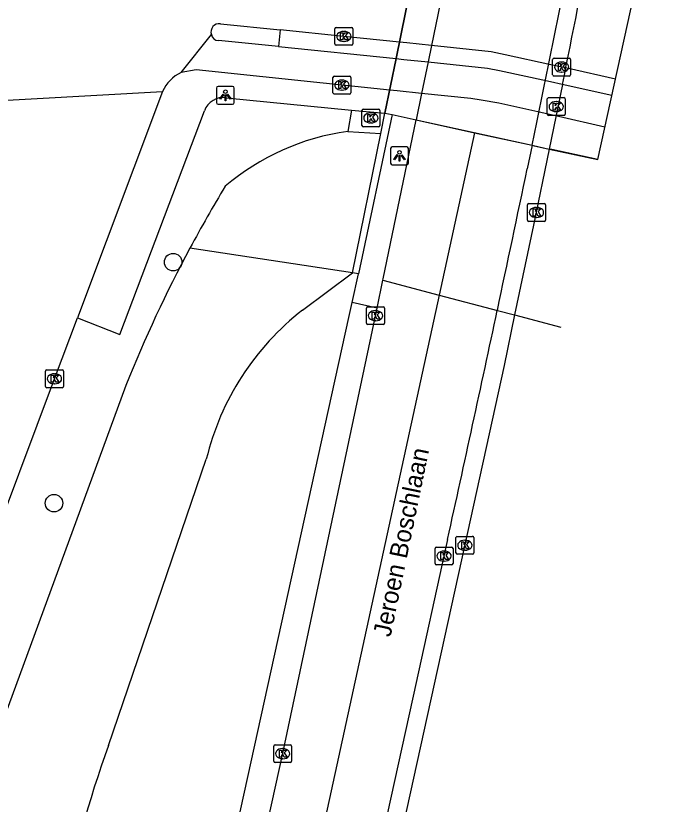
# Model space of a CAD drawing. Extents: x 162172 to 163187, y 382874 to 383684.
# Drawn here: x 163131.97 to 163168.94, y 383006.21 to 383050.22 of the extents above; entities that cross this region are included whole.
import ezdxf

# ---------------------------------------------------------------- set-up
doc = ezdxf.new("R2010")
doc.units = 0
for name, color, linetype in [('IMGEO_Berm_gesloten', 7, 'Continuous'), ('IMGEO_Berm_groen', 7, 'Continuous'), ('IMGEO_Berm_open', 7, 'Continuous'), ('IMGEO_Boom', 7, 'Continuous'), ('IMGEO_Dek', 7, 'Continuous'), ('IMGEO_Fietspad_open', 7, 'Continuous'), ('IMGEO_Hek', 7, 'Continuous'), ('IMGEO_Kolk', 7, 'Continuous'), ('IMGEO_Lichtpunt', 7, 'Continuous'), ('IMGEO_Muur', 7, 'Continuous'), ('IMGEO_Openbare_ruimte_label', 7, 'Continuous'), ('IMGEO_Rijbaan_lokaal_gesloten', 7, 'Continuous'), ('IMGEO_Rijbaan_lokaal_open', 7, 'Continuous'), ('IMGEO_Rijbaan_regionaal_gesloten', 7, 'Continuous'), ('IMGEO_Verkeerseiland_open', 7, 'Continuous'), ('IMGEO_Voetpad_open', 7, 'Continuous')]:
    doc.layers.add(name, color=color, linetype=linetype)

msp = doc.modelspace()

# ---------------------------------------------------------------- linework, layer by layer
at = {"layer": 'IMGEO_Berm_gesloten'}
msp.add_lwpolyline([(163158.847, 383033.776), (163159.814, 383033.521)], dxfattribs=at)
at = {"layer": 'IMGEO_Berm_groen'}
for points in [[(163150.71, 383044.959), (163150.497, 383043.765)], [(163147.971, 383033.794), (163150.756, 383035.866)], [(163132.311, 382950.327), (163150.561, 383033.379), (163150.743, 383034.209)], [(163138.112, 383029.587), (163130.709, 383009.426)], [(163137.146, 383009.486), (163142.599, 383025.464)]]:
    msp.add_lwpolyline(points, dxfattribs=at)
for centre, radius, start, end in [((163208.22, 383001.542), 75.51, 151.77482, 158.19712), ((163157.287, 383021.889), 15.117, 128.0444, 166.3198), ((163191.568, 382989.56), 57.955, 159.89074, 169.62253)]:
    msp.add_arc(centre, radius, start, end, dxfattribs=at)
at = {"layer": 'IMGEO_Berm_open'}
for points in [[(163158.23, 383064.942), (163156.885, 383065.236), (163156.496, 383065.321), (163156.083, 383063.015), (163155.711, 383060.937), (163155.55, 383060.039), (163154.667, 383055.107), (163154.492, 383054.187), (163153.196, 383047.828), (163152.574, 383044.776), (163152.973, 383044.701), (163154.313, 383044.408)], [(163150.497, 383043.765), (163152.344, 383043.65)], [(163160.79, 383042.99), (163161.74, 383042.782)], [(163150.756, 383035.866), (163141.689, 383037.253)], [(163150.743, 383034.209), (163151.096, 383035.814)], [(163152.139, 383033.902), (163150.743, 383034.209)]]:
    msp.add_lwpolyline(points, dxfattribs=at)
for centre, radius, start, end in [((163152.32, 383030.535), 13.355, 97.8457, 130.4348), ((163209.121, 383001.02), 76.55, 148.77827, 151.74987)]:
    msp.add_arc(centre, radius, start, end, dxfattribs=at)
at = {"layer": 'IMGEO_Boom'}
for centre in [(163140.748, 383036.468), (163134.101, 383023.01)]:
    msp.add_circle(centre, 0.489, dxfattribs=at)
at = {"layer": 'IMGEO_Dek'}
msp.add_lwpolyline([(163164.453, 383042.189), (163166.656, 383052.2), (163168.944, 383062.596), (163168.818, 383062.624), (163165.733, 383063.299), (163164.764, 383063.511), (163158.23, 383064.942), (163156.885, 383065.236), (163156.496, 383065.321), (163156.083, 383063.015), (163155.711, 383060.937), (163155.55, 383060.039), (163154.667, 383055.107), (163154.492, 383054.187), (163153.196, 383047.828), (163152.574, 383044.776), (163152.973, 383044.701), (163154.313, 383044.408), (163160.79, 383042.99), (163161.74, 383042.782), (163164.453, 383042.189)], dxfattribs=at)
at = {"layer": 'IMGEO_Fietspad_open'}
for points in [[(163146.629, 383048.51), (163143.275, 383048.842)], [(163146.629, 383048.51), (163153.196, 383047.828), (163153.618, 383047.784), (163154.983, 383047.642), (163158.292, 383047.294), (163158.975, 383047.168), (163161.644, 383046.581), (163162.627, 383046.365), (163165.245, 383045.789)], [(163164.853, 383044.008), (163162.269, 383044.59), (163161.283, 383044.812), (163158.936, 383045.34), (163157.941, 383045.503), (163157.376, 383045.596), (163154.619, 383045.886), (163153.251, 383046.029), (163152.839, 383046.073), (163142.029, 383047.204), (163141.189, 383047.059)]]:
    msp.add_lwpolyline(points, dxfattribs=at)
msp.add_arc((163143.275, 383049.234), 0.392, 189.5261, 269.9347, dxfattribs=at)
at = {"layer": 'IMGEO_Hek'}
for points in [[(163153.196, 383047.828), (163154.492, 383054.187)], [(163152.574, 383044.776), (163153.196, 383047.828)]]:
    msp.add_lwpolyline(points, dxfattribs=at)
at = {"layer": 'IMGEO_Kolk'}
for p, q in [((163149.779, 383048.645), (163149.779, 383049.497)), ((163149.854, 383049.571), (163150.706, 383049.571)), ((163150.267, 383049.351), (163150.292, 383049.351)), ((163150.78, 383049.497), (163150.78, 383048.645)), ((163150.706, 383048.571), (163149.854, 383048.571)), ((163150.29, 383048.791), (163150.265, 383048.791)), ((163161.935, 383046.932), (163161.935, 383047.784)), ((163162.01, 383047.858), (163162.862, 383047.858)), ((163162.423, 383047.638), (163162.448, 383047.638)), ((163162.936, 383047.784), (163162.936, 383046.932)), ((163162.446, 383047.078), (163162.421, 383047.078)), ((163149.671, 383045.926), (163149.671, 383046.778)), ((163149.746, 383046.852), (163150.598, 383046.852)), ((163150.159, 383046.632), (163150.184, 383046.632)), ((163150.672, 383046.778), (163150.672, 383045.926)), ((163162.862, 383046.858), (163162.01, 383046.858)), ((163150.598, 383045.852), (163149.746, 383045.852)), ((163150.182, 383046.072), (163150.157, 383046.072)), ((163161.635, 383044.724), (163161.635, 383045.576)), ((163161.71, 383045.65), (163162.562, 383045.65)), ((163162.123, 383045.43), (163162.148, 383045.43)), ((163162.636, 383045.576), (163162.636, 383044.724)), ((163151.288, 383044.089), (163151.288, 383044.941)), ((163151.363, 383045.015), (163152.215, 383045.015)), ((163152.289, 383044.941), (163152.289, 383044.089)), ((163162.146, 383044.87), (163162.121, 383044.87)), ((163151.776, 383044.795), (163151.801, 383044.795)), ((163162.562, 383044.65), (163161.71, 383044.65)), ((163152.215, 383044.015), (163151.363, 383044.015)), ((163151.799, 383044.235), (163151.774, 383044.235)), ((163160.53, 383038.814), (163160.53, 383039.666)), ((163160.605, 383039.74), (163161.457, 383039.74)), ((163161.531, 383039.666), (163161.531, 383038.814)), ((163161.018, 383039.52), (163161.043, 383039.52)), ((163161.457, 383038.74), (163160.605, 383038.74)), ((163161.041, 383038.96), (163161.016, 383038.96)), ((163151.545, 383033.053), (163151.545, 383033.905)), ((163151.62, 383033.979), (163152.472, 383033.979)), ((163152.546, 383033.905), (163152.546, 383033.053)), ((163152.033, 383033.759), (163152.058, 383033.759)), ((163152.472, 383032.979), (163151.62, 383032.979)), ((163152.056, 383033.199), (163152.031, 383033.199)), ((163133.625, 383029.533), (163133.625, 383030.385)), ((163133.7, 383030.459), (163134.552, 383030.459)), ((163134.626, 383030.385), (163134.626, 383029.533)), ((163134.113, 383030.239), (163134.138, 383030.239)), ((163134.552, 383029.459), (163133.7, 383029.459)), ((163134.136, 383029.679), (163134.111, 383029.679)), ((163156.536, 383020.235), (163156.536, 383021.087)), ((163156.611, 383021.161), (163157.463, 383021.161)), ((163157.537, 383021.087), (163157.537, 383020.235)), ((163157.024, 383020.941), (163157.049, 383020.941)), ((163155.371, 383019.636), (163155.371, 383020.488)), ((163155.446, 383020.562), (163156.298, 383020.562)), ((163155.859, 383020.342), (163155.884, 383020.342)), ((163156.372, 383020.488), (163156.372, 383019.636)), ((163157.047, 383020.381), (163157.022, 383020.381)), ((163155.882, 383019.782), (163155.857, 383019.782)), ((163157.463, 383020.161), (163156.611, 383020.161)), ((163156.298, 383019.562), (163155.446, 383019.562)), ((163146.363, 383008.603), (163146.363, 383009.455)), ((163146.438, 383009.529), (163147.29, 383009.529)), ((163146.851, 383009.309), (163146.876, 383009.309)), ((163147.364, 383009.455), (163147.364, 383008.603)), ((163146.874, 383008.749), (163146.849, 383008.749)), ((163147.29, 383008.529), (163146.438, 383008.529))]:
    msp.add_line(p, q, dxfattribs=at)
for points in [[(163149.779, 383048.645), (163149.779, 383049.497)], [(163149.854, 383049.571), (163150.706, 383049.571)], [(163150.1, 383049.271), (163150.223, 383049.271), (163150.223, 383049.12), (163150.353, 383049.271), (163150.517, 383049.271), (163150.371, 383049.12), (163150.524, 383048.871), (163150.372, 383048.871), (163150.287, 383049.035), (163150.223, 383048.968), (163150.223, 383048.871), (163150.1, 383048.871), (163150.1, 383049.271)], [(163150.78, 383049.497), (163150.78, 383048.645)], [(163150.706, 383048.571), (163149.854, 383048.571)], [(163161.935, 383046.932), (163161.935, 383047.784)], [(163162.01, 383047.858), (163162.862, 383047.858)], [(163162.256, 383047.558), (163162.379, 383047.558), (163162.379, 383047.407), (163162.509, 383047.558), (163162.673, 383047.558), (163162.527, 383047.407), (163162.68, 383047.158), (163162.528, 383047.158), (163162.443, 383047.322), (163162.379, 383047.255), (163162.379, 383047.158), (163162.256, 383047.158), (163162.256, 383047.558)], [(163162.936, 383047.784), (163162.936, 383046.932)], [(163149.671, 383045.926), (163149.671, 383046.778)], [(163149.746, 383046.852), (163150.598, 383046.852)], [(163150.672, 383046.778), (163150.672, 383045.926)], [(163162.862, 383046.858), (163162.01, 383046.858)], [(163149.992, 383046.552), (163150.115, 383046.552), (163150.115, 383046.401), (163150.245, 383046.552), (163150.409, 383046.552), (163150.263, 383046.401), (163150.416, 383046.152), (163150.264, 383046.152), (163150.179, 383046.316), (163150.115, 383046.249), (163150.115, 383046.152), (163149.992, 383046.152), (163149.992, 383046.552)], [(163150.598, 383045.852), (163149.746, 383045.852)], [(163161.635, 383044.724), (163161.635, 383045.576)], [(163161.71, 383045.65), (163162.562, 383045.65)], [(163161.956, 383045.35), (163162.079, 383045.35), (163162.079, 383045.199), (163162.209, 383045.35), (163162.373, 383045.35), (163162.227, 383045.199), (163162.38, 383044.95), (163162.228, 383044.95), (163162.143, 383045.114), (163162.079, 383045.047), (163162.079, 383044.95), (163161.956, 383044.95), (163161.956, 383045.35)], [(163162.636, 383045.576), (163162.636, 383044.724)], [(163151.288, 383044.089), (163151.288, 383044.941)], [(163151.363, 383045.015), (163152.215, 383045.015)], [(163152.289, 383044.941), (163152.289, 383044.089)], [(163151.609, 383044.715), (163151.732, 383044.715), (163151.732, 383044.564), (163151.862, 383044.715), (163152.026, 383044.715), (163151.88, 383044.564), (163152.033, 383044.315), (163151.881, 383044.315), (163151.796, 383044.479), (163151.732, 383044.412), (163151.732, 383044.315), (163151.609, 383044.315), (163151.609, 383044.715)], [(163162.562, 383044.65), (163161.71, 383044.65)], [(163152.215, 383044.015), (163151.363, 383044.015)], [(163160.53, 383038.814), (163160.53, 383039.666)], [(163160.605, 383039.74), (163161.457, 383039.74)], [(163161.531, 383039.666), (163161.531, 383038.814)], [(163160.851, 383039.44), (163160.974, 383039.44), (163160.974, 383039.289), (163161.104, 383039.44), (163161.268, 383039.44), (163161.122, 383039.289), (163161.275, 383039.04), (163161.123, 383039.04), (163161.038, 383039.204), (163160.974, 383039.137), (163160.974, 383039.04), (163160.851, 383039.04), (163160.851, 383039.44)], [(163161.457, 383038.74), (163160.605, 383038.74)], [(163151.545, 383033.053), (163151.545, 383033.905)], [(163151.62, 383033.979), (163152.472, 383033.979)], [(163152.546, 383033.905), (163152.546, 383033.053)], [(163151.866, 383033.679), (163151.989, 383033.679), (163151.989, 383033.528), (163152.119, 383033.679), (163152.283, 383033.679), (163152.137, 383033.528), (163152.29, 383033.279), (163152.138, 383033.279), (163152.053, 383033.443), (163151.989, 383033.376), (163151.989, 383033.279), (163151.866, 383033.279), (163151.866, 383033.679)], [(163152.472, 383032.979), (163151.62, 383032.979)], [(163133.625, 383029.533), (163133.625, 383030.385)], [(163133.7, 383030.459), (163134.552, 383030.459)], [(163134.626, 383030.385), (163134.626, 383029.533)], [(163133.946, 383030.159), (163134.069, 383030.159), (163134.069, 383030.008), (163134.199, 383030.159), (163134.363, 383030.159), (163134.217, 383030.008), (163134.37, 383029.759), (163134.218, 383029.759), (163134.133, 383029.923), (163134.069, 383029.856), (163134.069, 383029.759), (163133.946, 383029.759), (163133.946, 383030.159)], [(163134.552, 383029.459), (163133.7, 383029.459)], [(163156.536, 383020.235), (163156.536, 383021.087)], [(163156.611, 383021.161), (163157.463, 383021.161)], [(163157.537, 383021.087), (163157.537, 383020.235)], [(163156.857, 383020.861), (163156.98, 383020.861), (163156.98, 383020.71), (163157.11, 383020.861), (163157.274, 383020.861), (163157.128, 383020.71), (163157.281, 383020.461), (163157.129, 383020.461), (163157.044, 383020.625), (163156.98, 383020.558), (163156.98, 383020.461), (163156.857, 383020.461), (163156.857, 383020.861)], [(163155.371, 383019.636), (163155.371, 383020.488)], [(163155.446, 383020.562), (163156.298, 383020.562)], [(163155.692, 383020.262), (163155.815, 383020.262), (163155.815, 383020.111), (163155.945, 383020.262), (163156.109, 383020.262), (163155.963, 383020.111), (163156.116, 383019.862), (163155.964, 383019.862), (163155.879, 383020.026), (163155.815, 383019.959), (163155.815, 383019.862), (163155.692, 383019.862), (163155.692, 383020.262)], [(163156.372, 383020.488), (163156.372, 383019.636)], [(163157.463, 383020.161), (163156.611, 383020.161)], [(163156.298, 383019.562), (163155.446, 383019.562)], [(163146.363, 383008.603), (163146.363, 383009.455)], [(163146.438, 383009.529), (163147.29, 383009.529)], [(163146.684, 383009.229), (163146.807, 383009.229), (163146.807, 383009.078), (163146.937, 383009.229), (163147.101, 383009.229), (163146.955, 383009.078), (163147.108, 383008.829), (163146.956, 383008.829), (163146.871, 383008.993), (163146.807, 383008.926), (163146.807, 383008.829), (163146.684, 383008.829), (163146.684, 383009.229)], [(163147.364, 383009.455), (163147.364, 383008.603)], [(163147.29, 383008.529), (163146.438, 383008.529)]]:
    msp.add_lwpolyline(points, dxfattribs=at)
for centre, start, end in [((163149.856, 383049.495), 91.552, 178.448), ((163149.856, 383049.495), 91.552, 178.448), ((163150.704, 383049.495), 1.552, 88.448), ((163150.704, 383049.495), 1.552, 88.448), ((163149.856, 383048.647), 181.552, 268.448), ((163149.856, 383048.647), 181.552, 268.448), ((163150.704, 383048.647), 271.552, 358.448), ((163150.704, 383048.647), 271.552, 358.448), ((163162.012, 383047.782), 91.552, 178.448), ((163162.012, 383047.782), 91.552, 178.448), ((163162.86, 383047.782), 1.552, 88.448), ((163162.86, 383047.782), 1.552, 88.448), ((163149.748, 383046.776), 91.552, 178.448), ((163149.748, 383046.776), 91.552, 178.448), ((163150.596, 383046.776), 1.552, 88.448), ((163150.596, 383046.776), 1.552, 88.448), ((163162.012, 383046.934), 181.552, 268.448), ((163162.012, 383046.934), 181.552, 268.448), ((163162.86, 383046.934), 271.552, 358.448), ((163162.86, 383046.934), 271.552, 358.448), ((163149.748, 383045.928), 181.552, 268.448), ((163149.748, 383045.928), 181.552, 268.448), ((163150.596, 383045.928), 271.552, 358.448), ((163150.596, 383045.928), 271.552, 358.448), ((163161.712, 383045.574), 91.552, 178.448), ((163161.712, 383045.574), 91.552, 178.448), ((163162.56, 383045.574), 1.552, 88.448), ((163162.56, 383045.574), 1.552, 88.448), ((163151.365, 383044.939), 91.552, 178.448), ((163151.365, 383044.939), 91.552, 178.448), ((163152.213, 383044.939), 1.552, 88.448), ((163152.213, 383044.939), 1.552, 88.448), ((163161.712, 383044.726), 181.552, 268.448), ((163161.712, 383044.726), 181.552, 268.448), ((163162.56, 383044.726), 271.552, 358.448), ((163162.56, 383044.726), 271.552, 358.448), ((163151.365, 383044.091), 181.552, 268.448), ((163151.365, 383044.091), 181.552, 268.448), ((163152.213, 383044.091), 271.552, 358.448), ((163152.213, 383044.091), 271.552, 358.448), ((163160.607, 383039.664), 91.552, 178.448), ((163160.607, 383039.664), 91.552, 178.448), ((163161.455, 383039.664), 1.552, 88.448), ((163161.455, 383039.664), 1.552, 88.448), ((163160.607, 383038.816), 181.552, 268.448), ((163160.607, 383038.816), 181.552, 268.448), ((163161.455, 383038.816), 271.552, 358.448), ((163161.455, 383038.816), 271.552, 358.448), ((163151.622, 383033.903), 91.552, 178.448), ((163151.622, 383033.903), 91.552, 178.448), ((163152.47, 383033.903), 1.552, 88.448), ((163152.47, 383033.903), 1.552, 88.448), ((163151.622, 383033.055), 181.552, 268.448), ((163151.622, 383033.055), 181.552, 268.448), ((163152.47, 383033.055), 271.552, 358.448), ((163152.47, 383033.055), 271.552, 358.448), ((163133.702, 383030.383), 91.552, 178.448), ((163133.702, 383030.383), 91.552, 178.448), ((163134.55, 383030.383), 1.552, 88.448), ((163134.55, 383030.383), 1.552, 88.448), ((163133.702, 383029.535), 181.552, 268.448), ((163133.702, 383029.535), 181.552, 268.448), ((163134.55, 383029.535), 271.552, 358.448), ((163134.55, 383029.535), 271.552, 358.448), ((163156.613, 383021.085), 91.552, 178.448), ((163156.613, 383021.085), 91.552, 178.448), ((163157.461, 383021.085), 1.552, 88.448), ((163157.461, 383021.085), 1.552, 88.448), ((163155.448, 383020.486), 91.552, 178.448), ((163155.448, 383020.486), 91.552, 178.448), ((163156.296, 383020.486), 1.552, 88.448), ((163156.296, 383020.486), 1.552, 88.448), ((163156.613, 383020.237), 181.552, 268.448), ((163156.613, 383020.237), 181.552, 268.448), ((163157.461, 383020.237), 271.552, 358.448), ((163157.461, 383020.237), 271.552, 358.448), ((163155.448, 383019.638), 181.552, 268.448), ((163155.448, 383019.638), 181.552, 268.448), ((163156.296, 383019.638), 271.552, 358.448), ((163156.296, 383019.638), 271.552, 358.448), ((163146.44, 383009.453), 91.552, 178.448), ((163146.44, 383009.453), 91.552, 178.448), ((163147.288, 383009.453), 1.552, 88.448), ((163147.288, 383009.453), 1.552, 88.448), ((163146.44, 383008.605), 181.552, 268.448), ((163146.44, 383008.605), 181.552, 268.448), ((163147.288, 383008.605), 271.552, 358.448), ((163147.288, 383008.605), 271.552, 358.448)]:
    msp.add_arc(centre, 0.0765, start, end, dxfattribs=at)
for centre, major_axis, ratio, start_param, end_param in [((163150.266, 383049.071), (-0.387, 0.002), 0.722429, 4.712389, 7.853982), ((163150.291, 383049.071), (-0.39, 0.002), 0.717154, 1.570796, 4.712389), ((163162.422, 383047.358), (-0.387, 0.002), 0.722429, 4.712389, 7.853982), ((163162.447, 383047.358), (-0.39, 0.002), 0.717154, 1.570796, 4.712389), ((163150.158, 383046.352), (-0.387, 0.002), 0.722429, 4.712389, 7.853982), ((163150.183, 383046.352), (-0.39, 0.002), 0.717154, 1.570796, 4.712389), ((163162.122, 383045.15), (-0.387, 0.002), 0.722429, 4.712389, 7.853982), ((163162.147, 383045.15), (-0.39, 0.002), 0.717154, 1.570796, 4.712389), ((163151.775, 383044.515), (-0.387, 0.002), 0.722429, 4.712389, 7.853982), ((163151.8, 383044.515), (-0.39, 0.002), 0.717154, 1.570796, 4.712389), ((163161.017, 383039.24), (-0.387, 0.002), 0.722429, 4.712389, 7.853982), ((163161.042, 383039.24), (-0.39, 0.002), 0.717154, 1.570796, 4.712389), ((163152.032, 383033.479), (-0.387, 0.002), 0.722429, 4.712389, 7.853982), ((163152.057, 383033.479), (-0.39, 0.002), 0.717154, 1.570796, 4.712389), ((163134.112, 383029.959), (-0.387, 0.002), 0.722429, 4.712389, 7.853982), ((163134.137, 383029.959), (-0.39, 0.002), 0.717154, 1.570796, 4.712389), ((163157.023, 383020.661), (-0.387, 0.002), 0.722429, 4.712389, 7.853982), ((163157.048, 383020.661), (-0.39, 0.002), 0.717154, 1.570796, 4.712389), ((163155.858, 383020.062), (-0.387, 0.002), 0.722429, 4.712389, 7.853982), ((163155.883, 383020.062), (-0.39, 0.002), 0.717154, 1.570796, 4.712389), ((163146.85, 383009.029), (-0.387, 0.002), 0.722429, 4.712389, 7.853982), ((163146.875, 383009.029), (-0.39, 0.002), 0.717154, 1.570796, 4.712389)]:
    msp.add_ellipse(centre, major_axis=major_axis, ratio=ratio, start_param=start_param, end_param=end_param, dxfattribs=at)
at = {"layer": 'IMGEO_Lichtpunt'}
for p, q in [((163143.169, 383046.184), (163143.169, 383045.377)), ((163143.169, 383046.184), (163143.169, 383045.377)), ((163144.071, 383046.279), (163143.263, 383046.279)), ((163144.071, 383046.279), (163143.263, 383046.279)), ((163144.165, 383045.377), (163144.165, 383046.184)), ((163144.165, 383045.377), (163144.165, 383046.184)), ((163143.263, 383045.283), (163144.071, 383045.283)), ((163143.263, 383045.283), (163144.071, 383045.283)), ((163152.888, 383042.803), (163152.888, 383041.996)), ((163152.888, 383042.803), (163152.888, 383041.996)), ((163153.79, 383042.898), (163152.982, 383042.898)), ((163153.79, 383042.898), (163152.982, 383042.898)), ((163153.884, 383041.996), (163153.884, 383042.803)), ((163153.884, 383041.996), (163153.884, 383042.803)), ((163152.982, 383041.902), (163153.79, 383041.902)), ((163152.982, 383041.902), (163153.79, 383041.902))]:
    msp.add_line(p, q, dxfattribs=at)
for points in [[(163143.543, 383045.848), (163143.582, 383045.82), (163143.394, 383045.558), (163143.356, 383045.585), (163143.543, 383045.848)], [(163143.645, 383045.8), (163143.692, 383045.8), (163143.692, 383045.478), (163143.645, 383045.478), (163143.645, 383045.8)], [(163143.755, 383045.82), (163143.793, 383045.847), (163143.98, 383045.585), (163143.941, 383045.557), (163143.755, 383045.82)], [(163153.262, 383042.467), (163153.301, 383042.439), (163153.113, 383042.177), (163153.075, 383042.204), (163153.262, 383042.467)], [(163153.364, 383042.419), (163153.411, 383042.419), (163153.411, 383042.097), (163153.364, 383042.097), (163153.364, 383042.419)], [(163153.474, 383042.439), (163153.512, 383042.466), (163153.699, 383042.204), (163153.66, 383042.176), (163153.474, 383042.439)]]:
    msp.add_lwpolyline(points, dxfattribs=at)
for centre in [(163143.668, 383045.982), (163153.387, 383042.601)]:
    msp.add_circle(centre, 0.0994, dxfattribs=at)
for centre, start, end in [((163143.263, 383046.184), 90, 180), ((163143.263, 383046.184), 90, 180), ((163144.071, 383046.184), 0, 90), ((163144.071, 383046.184), 0, 90), ((163143.263, 383045.377), 180, 270), ((163143.263, 383045.377), 180, 270), ((163144.071, 383045.377), 270, 0), ((163144.071, 383045.377), 270, 360), ((163152.982, 383042.803), 90, 180), ((163152.982, 383042.803), 90, 180), ((163153.79, 383042.803), 0, 90), ((163153.79, 383042.803), 0, 90), ((163152.982, 383041.996), 180, 270), ((163152.982, 383041.996), 180, 270), ((163153.79, 383041.996), 270, 0), ((163153.79, 383041.996), 270, 360)]:
    msp.add_arc(centre, 0.0946, start, end, dxfattribs=at)
at = {"layer": 'IMGEO_Muur'}
for points in [[(163152.973, 383044.701), (163151.096, 383035.814)], [(163152.344, 383043.65), (163152.574, 383044.776)], [(163152.574, 383044.776), (163152.973, 383044.701)], [(163150.756, 383035.866), (163152.344, 383043.65)], [(163151.096, 383035.814), (163150.756, 383035.866)]]:
    msp.add_lwpolyline(points, dxfattribs=at)
at = {"layer": 'IMGEO_Rijbaan_lokaal_gesloten'}
for points in [[(163129.144, 383045.377), (163140.16, 383045.987)], [(163140.16, 383045.987), (163135.415, 383033.359)], [(163117.88, 382989.013), (163120.127, 382995.283), (163120.735, 382997.497), (163121.897, 383000.656), (163124.351, 383007.183), (163125.474, 383010.089), (163126.316, 383012.264), (163127.123, 383013.779), (163127.523, 383014.531), (163128.915, 383017.105), (163129.662, 383018.485), (163130.174, 383019.451), (163134.125, 383029.959), (163135.415, 383033.359)]]:
    msp.add_lwpolyline(points, dxfattribs=at)
at = {"layer": 'IMGEO_Rijbaan_lokaal_open'}
for points in [[(163143.389, 383049.761), (163146.722, 383049.443)], [(163165.443, 383046.689), (163162.81, 383047.275), (163161.829, 383047.49), (163159.289, 383048.042), (163158.5, 383048.205), (163155.172, 383048.556), (163153.79, 383048.702), (163153.383, 383048.745), (163150.28, 383049.072), (163146.722, 383049.443)], [(163141.189, 383047.059), (163142.889, 383049.169)]]:
    msp.add_lwpolyline(points, dxfattribs=at)
for centre, radius, start, end in [((163143.302, 383049.328), 0.442, 78.6035, 201.028), ((163142.145, 383045.112), 2.169, 116.1447, 156.2002)]:
    msp.add_arc(centre, radius, start, end, dxfattribs=at)
at = {"layer": 'IMGEO_Rijbaan_regionaal_gesloten'}
for points in [[(163158.23, 383064.942), (163157.828, 383062.631), (163157.467, 383060.552), (163157.311, 383059.654), (163156.479, 383054.87), (163156.447, 383054.716), (163156.258, 383053.8), (163155.172, 383048.556), (163154.983, 383047.642), (163154.619, 383045.886), (163154.313, 383044.408)], [(163162.48, 383046.382), (163161.74, 383042.782)], [(163152.461, 383035.455), (163152.476, 383035.529), (163154.313, 383044.408)], [(163154.313, 383044.408), (163160.79, 383042.99)], [(163154.313, 383044.408), (163157.578, 383043.693)], [(163157.578, 383043.693), (163155.601, 383034.629)], [(163157.578, 383043.693), (163160.79, 383042.99)], [(163161.74, 383042.782), (163160.867, 383038.533), (163159.814, 383033.521)], [(163160.79, 383042.99), (163160.517, 383041.682)], [(163164.453, 383042.189), (163161.898, 383042.748), (163161.74, 383042.782)], [(163152.139, 383033.902), (163152.461, 383035.455)], [(163152.461, 383035.455), (163155.601, 383034.629)], [(163155.601, 383034.629), (163126.849, 382902.775)], [(163155.601, 383034.629), (163158.847, 383033.776)], [(163133.84, 382949.988), (163134.631, 382953.616), (163135.247, 382956.514), (163135.282, 382956.678), (163137.436, 382966.222), (163142.077, 382987.26), (163144.883, 383000), (163146.857, 383008.965), (163152.139, 383033.902)], [(163159.814, 383033.521), (163159.222, 383030.703), (163156.838, 383019.849), (163149.595, 382986.838), (163145.001, 382965.971), (163140.367, 382944.826), (163135.01, 382920.742), (163131.045, 382902.718), (163130.862, 382901.889)], [(163159.814, 383033.521), (163162.396, 383032.842)], [(163156.069, 383020.988), (163154.151, 383012.232), (163151.454, 382999.976), (163149.255, 382989.968), (163147.31, 382981.165), (163144.827, 382969.851), (163140.973, 382952.343), (163136.681, 382932.889), (163132.729, 382915.039), (163130.06, 382902.945), (163129.875, 382902.107)]]:
    msp.add_lwpolyline(points, dxfattribs=at)
for centre, radius, start, end in [((162405.6, 383199.882), 771.315, 348.263667, 349.816401), ((162415.96, 383198.703), 761.901, 348.467597, 349.763108), ((161221.601, 383447.114), 1980.851, 347.955769, 348.189495), ((161354.727, 383418.998), 1844.788, 347.540565, 347.947001)]:
    msp.add_arc(centre, radius, start, end, dxfattribs=at)
at = {"layer": 'IMGEO_Verkeerseiland_open'}
msp.add_lwpolyline([(163146.722, 383049.443), (163146.629, 383048.51)], dxfattribs=at)
at = {"layer": 'IMGEO_Voetpad_open'}
for points in [[(163143.706, 383045.645), (163150.71, 383044.959)], [(163135.415, 383033.359), (163137.777, 383032.423), (163142.501, 383044.918)], [(163150.71, 383044.959), (163152.574, 383044.776)], [(163152.973, 383044.701), (163154.313, 383044.408)], [(163160.79, 383042.99), (163160.906, 383042.965), (163161.74, 383042.782)]]:
    msp.add_lwpolyline(points, dxfattribs=at)
msp.add_arc((163143.554, 383044.534), 1.121, 82.2262, 159.9806, dxfattribs=at)

# ---------------------------------------------------------------- texts
at = {"layer": 'IMGEO_Openbare_ruimte_label'}
msp.add_text('Jeroen Boschlaan', height=1, rotation=78.3416, dxfattribs=at).set_placement((163152.881, 383015.5))

doc.saveas('drawing.dxf')
